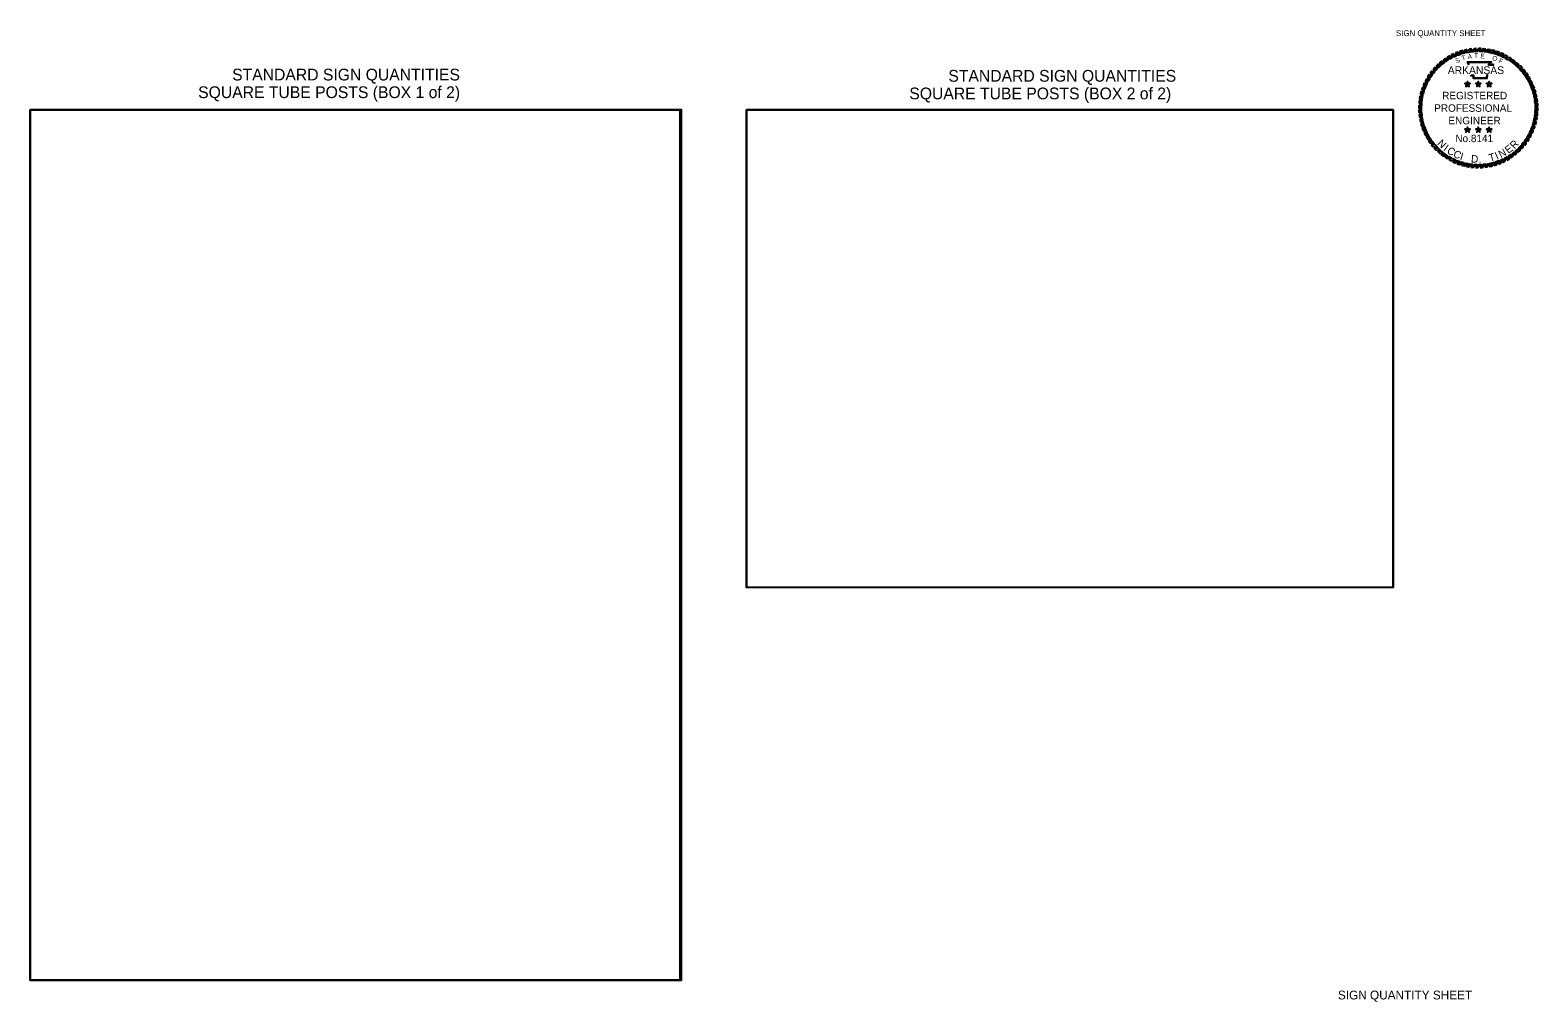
# Model space of a CAD drawing. Extents: x 1001889 to 1002131, y 1840840 to 1840908.
import ezdxf

# ---------------------------------------------------------------- set-up
doc = ezdxf.new("R2010")
doc.units = 0
for name, color, linetype in [('1', 7, 'Continuous'), ('43', 7, 'Continuous'), ('G-ANNO-SYMB', 7, 'Continuous'), ('G-ANNO-TEXT', 7, 'Continuous'), ('Level 10', 7, 'Continuous')]:
    doc.layers.add(name, color=color, linetype=linetype)

msp = doc.modelspace()

# ---------------------------------------------------------------- linework, layer by layer
at = {"layer": '1'}
for points in [[(1001889.375, 1840850.127), (1001929.292, 1840850.127), (1001929.292, 1840903.458), (1001889.375, 1840903.458)], [(1001933.265, 1840874.198), (1001972.894, 1840874.198), (1001972.894, 1840903.458), (1001933.265, 1840903.458)]]:
    msp.add_lwpolyline(points, close=True, dxfattribs=at)
at = {"layer": 'G-ANNO-SYMB'}
for points in [[(1001977.444, 1840907.157), (1001977.291, 1840907.124), (1001977.117, 1840906.906), (1001977.28, 1840906.95)], [(1001977.728, 1840907.198), (1001977.572, 1840907.178), (1001977.382, 1840906.974), (1001977.548, 1840907.006)], [(1001978.014, 1840907.218), (1001977.857, 1840907.21), (1001977.651, 1840907.021), (1001977.819, 1840907.04)], [(1001978.3, 1840907.215), (1001978.143, 1840907.219), (1001977.923, 1840907.047), (1001978.092, 1840907.053)], [(1001978.585, 1840907.189), (1001978.429, 1840907.206), (1001978.196, 1840907.052), (1001978.365, 1840907.044)], [(1001978.868, 1840907.141), (1001978.713, 1840907.17), (1001978.469, 1840907.035), (1001978.637, 1840907.014)], [(1001975.671, 1840906.277), (1001975.557, 1840906.169), (1001975.523, 1840905.891), (1001975.639, 1840906.015)], [(1001975.89, 1840906.46), (1001975.768, 1840906.362), (1001975.713, 1840906.088), (1001975.838, 1840906.202)], [(1001976.124, 1840906.626), (1001975.994, 1840906.538), (1001975.917, 1840906.269), (1001976.051, 1840906.373)], [(1001976.37, 1840906.773), (1001976.234, 1840906.695), (1001976.136, 1840906.433), (1001976.277, 1840906.526)], [(1001976.626, 1840906.9), (1001976.484, 1840906.833), (1001976.366, 1840906.58), (1001976.515, 1840906.662)], [(1001976.892, 1840907.007), (1001976.745, 1840906.951), (1001976.608, 1840906.708), (1001976.762, 1840906.778)], [(1001977.165, 1840907.093), (1001977.015, 1840907.049), (1001976.858, 1840906.817), (1001977.018, 1840906.874)], [(1001979.145, 1840907.072), (1001978.994, 1840907.113), (1001978.74, 1840906.997), (1001978.905, 1840906.962)], [(1001979.417, 1840906.98), (1001979.269, 1840907.033), (1001979.006, 1840906.937), (1001979.169, 1840906.89)], [(1001979.68, 1840906.868), (1001979.537, 1840906.932), (1001979.268, 1840906.857), (1001979.426, 1840906.797)], [(1001979.934, 1840906.735), (1001979.796, 1840906.81), (1001979.522, 1840906.757), (1001979.675, 1840906.685)], [(1001980.177, 1840906.583), (1001980.045, 1840906.669), (1001979.767, 1840906.637), (1001979.915, 1840906.553)], [(1001980.406, 1840906.412), (1001980.282, 1840906.508), (1001980.003, 1840906.498), (1001980.143, 1840906.403)], [(1001980.622, 1840906.224), (1001980.506, 1840906.329), (1001980.227, 1840906.341), (1001980.359, 1840906.235)], [(1001974.955, 1840905.388), (1001974.879, 1840905.25), (1001974.933, 1840904.976), (1001975.005, 1840905.129)], [(1001975.107, 1840905.631), (1001975.021, 1840905.499), (1001975.053, 1840905.221), (1001975.137, 1840905.369)], [(1001975.278, 1840905.86), (1001975.182, 1840905.736), (1001975.192, 1840905.457), (1001975.287, 1840905.597)], [(1001975.466, 1840906.076), (1001975.361, 1840905.96), (1001975.349, 1840905.681), (1001975.454, 1840905.813)], [(1001980.823, 1840906.019), (1001980.715, 1840906.133), (1001980.437, 1840906.167), (1001980.561, 1840906.051)], [(1001981.006, 1840905.799), (1001980.908, 1840905.921), (1001980.634, 1840905.977), (1001980.748, 1840905.852)], [(1001981.172, 1840905.566), (1001981.084, 1840905.695), (1001980.815, 1840905.772), (1001980.919, 1840905.638)], [(1001981.319, 1840905.32), (1001981.241, 1840905.456), (1001980.979, 1840905.554), (1001981.072, 1840905.412)], [(1001981.446, 1840905.063), (1001981.379, 1840905.205), (1001981.126, 1840905.323), (1001981.208, 1840905.175)], [(1001974.618, 1840904.599), (1001974.577, 1840904.448), (1001974.693, 1840904.194), (1001974.727, 1840904.36)], [(1001974.709, 1840904.871), (1001974.657, 1840904.723), (1001974.752, 1840904.46), (1001974.8, 1840904.623)], [(1001974.822, 1840905.134), (1001974.758, 1840904.991), (1001974.832, 1840904.722), (1001974.892, 1840904.88)], [(1001977.451, 1840905.024), (1001977.413, 1840905.076), (1001977.292, 1840905.076), (1001977.39, 1840905.005)], [(1001977.451, 1840905.024), (1001977.39, 1840905.005), (1001977.353, 1840904.889), (1001977.451, 1840904.961)], [(1001977.451, 1840905.024), (1001977.488, 1840905.076), (1001977.451, 1840905.191), (1001977.413, 1840905.076)], [(1001977.451, 1840905.024), (1001977.511, 1840905.005), (1001977.609, 1840905.076), (1001977.488, 1840905.076)], [(1001977.451, 1840905.024), (1001977.451, 1840904.961), (1001977.549, 1840904.889), (1001977.511, 1840905.005)], [(1001978.118, 1840905.024), (1001978.08, 1840905.076), (1001977.959, 1840905.076), (1001978.057, 1840905.005)], [(1001978.118, 1840905.024), (1001978.057, 1840905.005), (1001978.02, 1840904.889), (1001978.118, 1840904.961)], [(1001978.118, 1840905.024), (1001978.155, 1840905.076), (1001978.118, 1840905.191), (1001978.08, 1840905.076)], [(1001978.118, 1840905.024), (1001978.178, 1840905.005), (1001978.276, 1840905.076), (1001978.155, 1840905.076)], [(1001978.118, 1840905.024), (1001978.118, 1840904.961), (1001978.216, 1840904.889), (1001978.178, 1840905.005)], [(1001978.785, 1840905.024), (1001978.747, 1840905.076), (1001978.626, 1840905.076), (1001978.724, 1840905.005)], [(1001978.785, 1840905.024), (1001978.724, 1840905.005), (1001978.687, 1840904.889), (1001978.785, 1840904.961)], [(1001978.785, 1840905.024), (1001978.822, 1840905.076), (1001978.785, 1840905.191), (1001978.747, 1840905.076)], [(1001978.785, 1840905.024), (1001978.845, 1840905.005), (1001978.943, 1840905.076), (1001978.822, 1840905.076)], [(1001978.785, 1840905.024), (1001978.785, 1840904.961), (1001978.883, 1840904.889), (1001978.845, 1840905.005)], [(1001981.553, 1840904.798), (1001981.497, 1840904.944), (1001981.254, 1840905.082), (1001981.324, 1840904.927)], [(1001981.639, 1840904.524), (1001981.595, 1840904.675), (1001981.363, 1840904.831), (1001981.42, 1840904.672)], [(1001981.703, 1840904.245), (1001981.67, 1840904.399), (1001981.452, 1840904.573), (1001981.496, 1840904.409)], [(1001974.475, 1840903.754), (1001974.47, 1840903.597), (1001974.642, 1840903.377), (1001974.637, 1840903.546)], [(1001974.472, 1840903.468), (1001974.48, 1840903.311), (1001974.669, 1840903.105), (1001974.65, 1840903.273)], [(1001974.5, 1840904.039), (1001974.484, 1840903.883), (1001974.638, 1840903.65), (1001974.646, 1840903.819)], [(1001974.548, 1840904.322), (1001974.519, 1840904.167), (1001974.655, 1840903.923), (1001974.676, 1840904.091)], [(1001981.744, 1840903.962), (1001981.724, 1840904.117), (1001981.52, 1840904.308), (1001981.552, 1840904.142)], [(1001981.764, 1840903.676), (1001981.756, 1840903.833), (1001981.567, 1840904.039), (1001981.586, 1840903.87)], [(1001981.735, 1840903.104), (1001981.752, 1840903.26), (1001981.598, 1840903.494), (1001981.59, 1840903.324)], [(1001981.761, 1840903.39), (1001981.765, 1840903.546), (1001981.593, 1840903.767), (1001981.598, 1840903.597)], [(1001974.491, 1840903.182), (1001974.511, 1840903.026), (1001974.716, 1840902.836), (1001974.684, 1840903.002)], [(1001974.533, 1840902.899), (1001974.565, 1840902.745), (1001974.784, 1840902.571), (1001974.739, 1840902.734)], [(1001974.597, 1840902.619), (1001974.641, 1840902.469), (1001974.873, 1840902.312), (1001974.815, 1840902.472)], [(1001981.526, 1840902.273), (1001981.579, 1840902.421), (1001981.483, 1840902.683), (1001981.436, 1840902.521)], [(1001981.618, 1840902.544), (1001981.659, 1840902.696), (1001981.543, 1840902.95), (1001981.508, 1840902.784)], [(1001981.687, 1840902.822), (1001981.716, 1840902.976), (1001981.581, 1840903.221), (1001981.56, 1840903.053)], [(1001974.682, 1840902.346), (1001974.738, 1840902.199), (1001974.982, 1840902.062), (1001974.912, 1840902.216)], [(1001974.789, 1840902.08), (1001974.856, 1840901.939), (1001975.11, 1840901.82), (1001975.028, 1840901.969)], [(1001974.916, 1840901.824), (1001974.995, 1840901.688), (1001975.256, 1840901.59), (1001975.163, 1840901.731)], [(1001977.451, 1840902.231), (1001977.413, 1840902.283), (1001977.292, 1840902.283), (1001977.39, 1840902.212)], [(1001977.451, 1840902.231), (1001977.39, 1840902.212), (1001977.353, 1840902.096), (1001977.451, 1840902.168)], [(1001977.451, 1840902.231), (1001977.488, 1840902.283), (1001977.451, 1840902.398), (1001977.413, 1840902.283)], [(1001977.451, 1840902.231), (1001977.511, 1840902.212), (1001977.609, 1840902.283), (1001977.488, 1840902.283)], [(1001977.451, 1840902.231), (1001977.451, 1840902.168), (1001977.549, 1840902.096), (1001977.511, 1840902.212)], [(1001978.118, 1840902.231), (1001978.08, 1840902.283), (1001977.959, 1840902.283), (1001978.057, 1840902.212)], [(1001978.118, 1840902.231), (1001978.057, 1840902.212), (1001978.02, 1840902.096), (1001978.118, 1840902.168)], [(1001978.118, 1840902.231), (1001978.155, 1840902.283), (1001978.118, 1840902.398), (1001978.08, 1840902.283)], [(1001978.118, 1840902.231), (1001978.178, 1840902.212), (1001978.276, 1840902.283), (1001978.155, 1840902.283)], [(1001978.118, 1840902.231), (1001978.118, 1840902.168), (1001978.216, 1840902.096), (1001978.178, 1840902.212)], [(1001978.785, 1840902.231), (1001978.747, 1840902.283), (1001978.626, 1840902.283), (1001978.724, 1840902.212)], [(1001978.785, 1840902.231), (1001978.724, 1840902.212), (1001978.687, 1840902.096), (1001978.785, 1840902.168)], [(1001978.785, 1840902.231), (1001978.822, 1840902.283), (1001978.785, 1840902.398), (1001978.747, 1840902.283)], [(1001978.785, 1840902.231), (1001978.845, 1840902.212), (1001978.943, 1840902.283), (1001978.822, 1840902.283)], [(1001978.785, 1840902.231), (1001978.785, 1840902.168), (1001978.883, 1840902.096), (1001978.845, 1840902.212)], [(1001980.958, 1840901.283), (1001981.054, 1840901.407), (1001981.044, 1840901.687), (1001980.949, 1840901.547)], [(1001981.129, 1840901.513), (1001981.215, 1840901.644), (1001981.183, 1840901.922), (1001981.099, 1840901.775)], [(1001981.281, 1840901.756), (1001981.356, 1840901.893), (1001981.303, 1840902.168), (1001981.231, 1840902.014)], [(1001981.414, 1840902.009), (1001981.478, 1840902.153), (1001981.403, 1840902.422), (1001981.343, 1840902.263)], [(1001975.064, 1840901.578), (1001975.152, 1840901.448), (1001975.421, 1840901.371), (1001975.317, 1840901.505)], [(1001975.229, 1840901.344), (1001975.328, 1840901.222), (1001975.602, 1840901.167), (1001975.488, 1840901.292)], [(1001975.413, 1840901.125), (1001975.521, 1840901.011), (1001975.798, 1840900.977), (1001975.675, 1840901.093)], [(1001975.613, 1840900.92), (1001975.73, 1840900.815), (1001976.009, 1840900.803), (1001975.877, 1840900.908)], [(1001975.829, 1840900.732), (1001975.953, 1840900.636), (1001976.233, 1840900.646), (1001976.093, 1840900.741)], [(1001979.866, 1840900.371), (1001980.002, 1840900.449), (1001980.1, 1840900.711), (1001979.958, 1840900.617)], [(1001980.112, 1840900.518), (1001980.241, 1840900.606), (1001980.318, 1840900.875), (1001980.184, 1840900.771)], [(1001980.345, 1840900.683), (1001980.467, 1840900.782), (1001980.523, 1840901.056), (1001980.398, 1840900.942)], [(1001980.565, 1840900.867), (1001980.679, 1840900.975), (1001980.713, 1840901.252), (1001980.597, 1840901.129)], [(1001980.77, 1840901.067), (1001980.875, 1840901.184), (1001980.887, 1840901.463), (1001980.781, 1840901.331)], [(1001976.059, 1840900.561), (1001976.19, 1840900.475), (1001976.468, 1840900.507), (1001976.321, 1840900.591)], [(1001976.302, 1840900.409), (1001976.439, 1840900.333), (1001976.714, 1840900.387), (1001976.56, 1840900.459)], [(1001976.555, 1840900.276), (1001976.699, 1840900.212), (1001976.968, 1840900.286), (1001976.809, 1840900.346)], [(1001976.819, 1840900.163), (1001976.967, 1840900.111), (1001977.229, 1840900.206), (1001977.067, 1840900.254)], [(1001977.09, 1840900.072), (1001977.242, 1840900.031), (1001977.496, 1840900.147), (1001977.33, 1840900.181)], [(1001977.368, 1840900.002), (1001977.522, 1840899.973), (1001977.767, 1840900.109), (1001977.599, 1840900.13)], [(1001977.65, 1840899.954), (1001977.806, 1840899.938), (1001978.039, 1840900.092), (1001977.87, 1840900.1)], [(1001977.936, 1840899.929), (1001978.092, 1840899.924), (1001978.313, 1840900.097), (1001978.143, 1840900.091)], [(1001978.222, 1840899.926), (1001978.379, 1840899.934), (1001978.585, 1840900.123), (1001978.416, 1840900.104)], [(1001978.508, 1840899.945), (1001978.663, 1840899.965), (1001978.854, 1840900.17), (1001978.688, 1840900.138)], [(1001978.791, 1840899.987), (1001978.945, 1840900.019), (1001979.119, 1840900.238), (1001978.955, 1840900.193)], [(1001979.07, 1840900.051), (1001979.221, 1840900.095), (1001979.377, 1840900.327), (1001979.218, 1840900.269)], [(1001979.344, 1840900.136), (1001979.49, 1840900.192), (1001979.628, 1840900.436), (1001979.473, 1840900.366)], [(1001979.609, 1840900.243), (1001979.751, 1840900.31), (1001979.869, 1840900.564), (1001979.721, 1840900.482)]]:
    msp.add_lwpolyline(points, close=True, dxfattribs=at)
for points in [[(1001977.533, 1840906.219), (1001977.448, 1840906.403), (1001978.92, 1840906.404), (1001978.797, 1840906.25), (1001978.897, 1840906.251), (1001978.98, 1840906.252), (1001979.064, 1840906.243)], [(1001977.555, 1840906.229), (1001977.485, 1840906.38), (1001978.871, 1840906.381), (1001978.748, 1840906.226), (1001978.897, 1840906.228), (1001978.979, 1840906.229), (1001979.061, 1840906.22)], [(1001978.688, 1840905.603), (1001978.663, 1840905.582), (1001978.654, 1840905.552), (1001978.646, 1840905.475), (1001978.646, 1840905.374), (1001977.825, 1840905.374), (1001977.825, 1840905.511), (1001977.825, 1840905.542), (1001977.791, 1840905.552), (1001977.675, 1840905.552), (1001977.654, 1840905.583)], [(1001978.673, 1840905.621), (1001978.642, 1840905.596), (1001978.631, 1840905.556), (1001978.623, 1840905.477), (1001978.623, 1840905.397), (1001977.848, 1840905.397), (1001977.848, 1840905.511), (1001977.848, 1840905.559), (1001977.795, 1840905.575), (1001977.687, 1840905.575), (1001977.673, 1840905.596)]]:
    msp.add_lwpolyline(points, dxfattribs=at)
at = {"layer": 'Level 10'}
for points in [[(1001889.375, 1840903.458), (1001929.196, 1840903.458), (1001929.196, 1840850.127), (1001889.375, 1840850.127)], [(1001933.265, 1840903.458), (1001972.894, 1840903.458), (1001972.894, 1840874.189), (1001933.265, 1840874.189)]]:
    msp.add_lwpolyline(points, close=True, dxfattribs=at)

# ---------------------------------------------------------------- texts
at = {"layer": '43'}
for s, p in [('STANDARD SIGN QUANTITIES', (1001901.751, 1840905.263)), ('STANDARD SIGN QUANTITIES', (1001945.641, 1840905.187)), ('SQUARE TUBE POSTS (BOX 1 of 2)', (1001899.67, 1840904.183)), ('SQUARE TUBE POSTS (BOX 2 of 2)', (1001943.249, 1840904.107))]:
    msp.add_text(s, height=0.72, rotation=360, dxfattribs=at).set_placement(p)
at = {"layer": 'G-ANNO-SYMB'}
for s, height, rotation, p in [('S', 0.29, 19.77256, (1001976.767, 1840906.316)), ('T', 0.29, 16.90148, (1001977.136, 1840906.481)), ('A', 0.29, 8.67877, (1001977.489, 1840906.573)), ('T', 0.29, 1.47887, (1001977.863, 1840906.631)), ('E', 0.29, 356.67203, (1001978.235, 1840906.622)), ('O', 0.29, 341.2218, (1001978.939, 1840906.523)), ('F', 0.29, 335.36282, (1001979.331, 1840906.37)), ('N', 0.459, 315.26758, (1001975.57, 1840901.372)), ('I', 0.459, 324.21406, (1001975.943, 1840901.002)), ('C', 0.459, 328.68731, (1001976.15, 1840900.841)), ('C', 0.459, 336.51548, (1001976.54, 1840900.598)), ('I', 0.459, 344.34365, (1001976.96, 1840900.411)), ('D', 0.459, 356.64507, (1001977.66, 1840900.237)), ('T', 0.459, 16.77466, (1001978.836, 1840900.283)), ('I', 0.459, 24.23006, (1001979.256, 1840900.404)), ('N', 0.459, 28.7033, (1001979.5, 1840900.502)), ('E', 0.459, 37.64979, (1001979.96, 1840900.754)), ('R', 0.459, 45.47796, (1001980.327, 1840901.032)), ('.', 0.459, 4.84601, (1001978.14, 1840900.206))]:
    msp.add_text(s, height=height, rotation=rotation, dxfattribs=at).set_placement(p)
for s, height, p in [('ARKANSAS', 0.4737, (1001976.246, 1840905.656)), ('REGISTERED', 0.4585, (1001975.902, 1840904.109)), ('PROFESSIONAL', 0.45855, (1001975.41, 1840903.343)), ('ENGINEER', 0.4585, (1001976.284, 1840902.576)), ('No.8141', 0.4567, (1001976.711, 1840901.483))]:
    msp.add_text(s, height=height, dxfattribs=at).set_placement(p)
at = {"layer": 'G-ANNO-TEXT'}
for height, p in [(0.36, (1001973.072, 1840907.982)), (0.54, (1001969.514, 1840848.937))]:
    msp.add_text('SIGN QUANTITY SHEET', height=height, dxfattribs=at).set_placement(p)

doc.saveas('drawing.dxf')
